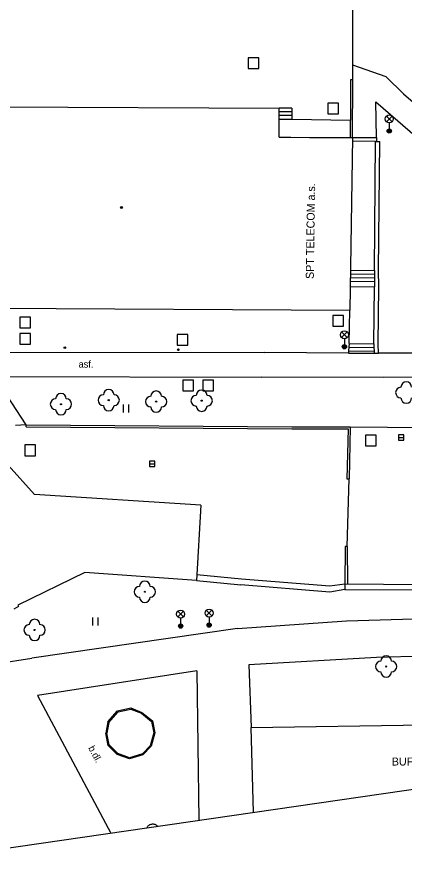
# Model space of a CAD drawing. Extents: x -641829 to -641525, y -1114855 to -1114359.
# Drawn here: x -641668.4 to -641632.1, y -1114854.7 to -1114774 of the extents above; entities that cross this region are included whole.
import ezdxf

# ---------------------------------------------------------------- set-up
doc = ezdxf.new("R2010")
doc.units = 0
for name, color, linetype in [('Vrstva 1', 7, 'Continuous'), ('Vrstva 10', 7, 'Continuous'), ('Vrstva 11', 7, 'Continuous'), ('Vrstva 20', 7, 'Continuous'), ('Vrstva 22', 7, 'Continuous'), ('Vrstva 26', 7, 'Continuous'), ('Vrstva 27', 7, 'Continuous'), ('Vrstva 33', 7, 'Continuous'), ('Vrstva 36', 7, 'Continuous'), ('Vrstva 39', 7, 'Continuous'), ('Vrstva 40', 7, 'Continuous'), ('Vrstva 41', 7, 'Continuous'), ('Vrstva 5', 7, 'Continuous'), ('Vrstva 7', 7, 'Continuous'), ('Vrstva 8', 7, 'Continuous')]:
    doc.layers.add(name, color=color, linetype=linetype)

msp = doc.modelspace()

# ---------------------------------------------------------------- linework, layer by layer
at = {"layer": 'Vrstva 1'}
msp.add_line((-641689.21, -1114854.71), (-641533.66, -1114832.21), dxfattribs=at)
at = {"layer": 'Vrstva 10'}
for p, q in [((-641633.81, -1114779.59), (-641636.93, -1114778.5)), ((-641632.18, -1114781.17), (-641633.81, -1114779.59)), ((-641632.18, -1114781.17), (-641620.12, -1114791.56)), ((-641637.17, -1114812.37), (-641622.59, -1114812.52))]:
    msp.add_line(p, q, dxfattribs=at)
at = {"layer": 'Vrstva 11'}
for p, q in [((-641634.75, -1114781.92), (-641627.17, -1114788.53)), ((-641634.71, -1114785.26), (-641634.75, -1114781.92)), ((-641642.62, -1114782.51), (-641643.82, -1114782.5)), ((-641642.62, -1114782.86), (-641643.82, -1114782.85)), ((-641642.62, -1114782.51), (-641642.62, -1114782.86)), ((-641642.62, -1114782.86), (-641642.62, -1114783.21)), ((-641642.62, -1114783.21), (-641643.82, -1114783.2)), ((-641643.82, -1114783.54), (-641642.62, -1114783.55)), ((-641642.62, -1114783.21), (-641642.62, -1114783.55)), ((-641642.62, -1114783.55), (-641637.14, -1114783.65)), ((-641636.95, -1114785.27), (-641634.71, -1114785.26)), ((-641634.71, -1114785.26), (-641634.71, -1114785.65)), ((-641634.79, -1114785.65), (-641636.95, -1114785.62)), ((-641634.9, -1114797.71), (-641634.79, -1114785.65)), ((-641634.79, -1114785.65), (-641634.71, -1114785.65)), ((-641634.71, -1114785.65), (-641634.39, -1114785.65)), ((-641634.5, -1114797.71), (-641634.39, -1114785.65)), ((-641637.14, -1114798.03), (-641634.9, -1114798.06)), ((-641637.13, -1114797.68), (-641634.9, -1114797.71)), ((-641634.9, -1114797.71), (-641634.9, -1114798.06)), ((-641634.9, -1114798.06), (-641634.9, -1114798.41)), ((-641634.49, -1114799.24), (-641634.5, -1114797.71)), ((-641637.15, -1114798.73), (-641634.89, -1114798.76)), ((-641637.14, -1114798.38), (-641634.9, -1114798.41)), ((-641634.9, -1114798.41), (-641634.89, -1114798.76)), ((-641634.89, -1114798.76), (-641634.89, -1114799.24)), ((-641637.16, -1114799.21), (-641634.89, -1114799.24)), ((-641634.94, -1114804.59), (-641634.89, -1114799.24)), ((-641634.54, -1114804.59), (-641634.49, -1114799.24)), ((-641637.26, -1114804.56), (-641637.19, -1114801.45)), ((-641637.26, -1114804.56), (-641637.29, -1114804.91)), ((-641637.26, -1114804.56), (-641634.94, -1114804.59)), ((-641634.94, -1114804.59), (-641634.94, -1114804.94)), ((-641634.53, -1114805.48), (-641634.54, -1114804.59)), ((-641670.92, -1114805.37), (-641645.18, -1114805.42)), ((-641637.34, -1114805.48), (-641645.18, -1114805.42)), ((-641637.32, -1114805.26), (-641637.34, -1114805.48)), ((-641637.34, -1114805.48), (-641634.93, -1114805.48)), ((-641637.29, -1114804.91), (-641637.32, -1114805.26)), ((-641637.32, -1114805.26), (-641634.93, -1114805.29)), ((-641637.29, -1114804.91), (-641634.94, -1114804.94)), ((-641634.94, -1114804.94), (-641634.93, -1114805.29)), ((-641634.93, -1114805.29), (-641634.93, -1114805.48)), ((-641634.93, -1114805.48), (-641634.53, -1114805.48)), ((-641621.75, -1114805.43), (-641634.53, -1114805.48)), ((-641670.49, -1114807.66), (-641645.43, -1114807.71)), ((-641667.52, -1114812.18), (-641670.49, -1114807.66)), ((-641634.02, -1114807.75), (-641645.43, -1114807.71)), ((-641621.92, -1114807.67), (-641634.02, -1114807.75)), ((-641637.68, -1114827.61), (-641611.8, -1114827.76)), ((-641647.71, -1114831.26), (-641637.5, -1114830.54)), ((-641637.5, -1114830.54), (-641620.39, -1114830.05)), ((-641647.71, -1114831.26), (-641667, -1114834.04)), ((-641612.75, -1114833.36), (-641634.7, -1114833.98)), ((-641681.11, -1114836.22), (-641667, -1114834.04)), ((-641634.7, -1114833.98), (-641646.67, -1114834.67)), ((-641651.53, -1114835.24), (-641666.47, -1114837.53)), ((-641651.53, -1114835.24), (-641651.335, -1114849.232)), ((-641646.67, -1114834.67), (-641646.44, -1114840.53)), ((-641666.47, -1114837.53), (-641659.603, -1114850.427)), ((-641659.86, -1114840.02), (-641658.96, -1114838.98)), ((-641659.77, -1114840.06), (-641658.91, -1114839.07)), ((-641658.96, -1114838.98), (-641657.71, -1114838.71)), ((-641658.91, -1114839.07), (-641657.72, -1114838.81)), ((-641657.72, -1114838.81), (-641656.72, -1114839.21)), ((-641657.71, -1114838.71), (-641656.67, -1114839.12)), ((-641656.72, -1114839.21), (-641655.79, -1114839.98)), ((-641656.67, -1114839.12), (-641655.7, -1114839.92)), ((-641659.86, -1114840.02), (-641660.07, -1114841.08)), ((-641659.77, -1114840.06), (-641659.97, -1114841.08)), ((-641655.79, -1114839.98), (-641655.57, -1114841.03)), ((-641655.7, -1114839.92), (-641655.47, -1114841.03)), ((-641655.57, -1114841.03), (-641655.89, -1114842.25)), ((-641655.47, -1114841.03), (-641655.8, -1114842.3)), ((-641659.84, -1114842.22), (-641660.07, -1114841.08)), ((-641659.75, -1114842.17), (-641659.97, -1114841.08)), ((-641658.98, -1114843.07), (-641659.84, -1114842.22)), ((-641658.92, -1114842.98), (-641659.75, -1114842.17)), ((-641655.89, -1114842.25), (-641656.63, -1114843.01)), ((-641655.8, -1114842.3), (-641656.58, -1114843.1)), ((-641657.84, -1114843.48), (-641658.98, -1114843.07)), ((-641657.84, -1114843.37), (-641658.92, -1114842.98)), ((-641656.63, -1114843.01), (-641657.84, -1114843.37)), ((-641656.58, -1114843.1), (-641657.84, -1114843.48)), ((-641656.214, -1114849.937), (-641656.19, -1114849.89)), ((-641656.19, -1114849.89), (-641656.16, -1114849.83)), ((-641656.16, -1114849.83), (-641656.11, -1114849.77)), ((-641656.11, -1114849.77), (-641656.06, -1114849.73)), ((-641656.06, -1114849.73), (-641656.01, -1114849.68)), ((-641656.01, -1114849.68), (-641655.95, -1114849.64)), ((-641655.95, -1114849.64), (-641655.89, -1114849.61)), ((-641655.89, -1114849.61), (-641655.82, -1114849.59)), ((-641655.82, -1114849.59), (-641655.76, -1114849.58)), ((-641655.76, -1114849.58), (-641655.69, -1114849.57)), ((-641655.69, -1114849.57), (-641655.62, -1114849.57)), ((-641655.62, -1114849.57), (-641655.55, -1114849.58)), ((-641655.55, -1114849.58), (-641655.48, -1114849.6)), ((-641655.48, -1114849.6), (-641655.42, -1114849.62)), ((-641655.42, -1114849.62), (-641655.36, -1114849.65)), ((-641655.36, -1114849.65), (-641655.3, -1114849.69)), ((-641655.3, -1114849.69), (-641655.25, -1114849.74)), ((-641655.25, -1114849.74), (-641655.2, -1114849.79)), ((-641655.2, -1114849.79), (-641655.2, -1114849.79))]:
    msp.add_line(p, q, dxfattribs=at)
msp.add_lwpolyline([(-641612.23, -1114827.33), (-641637.68, -1114827.12)], dxfattribs=at)
at = {"layer": 'Vrstva 20'}
for centre, radius in [((-641663.9, -1114804.96), 0.075), ((-641663.9, -1114804.96), 0.0204), ((-641653.26, -1114805.15), 0.075), ((-641653.26, -1114805.15), 0.0204)]:
    msp.add_circle(centre, radius, dxfattribs=at)
at = {"layer": 'Vrstva 22'}
for centre in [(-641664.26, -1114810.25), (-641659.79, -1114809.87), (-641655.34, -1114810.01), (-641651.08, -1114809.92), (-641656.4, -1114827.82), (-641666.73, -1114831.4), (-641633.8, -1114834.82)]:
    msp.add_circle(centre, 0.05, dxfattribs=at)
for centre, start, end in [((-641632.41, -1114809.16), 90, 270), ((-641631.91, -1114808.66), 0, 180), ((-641664.26, -1114809.75), 0, 180), ((-641660.29, -1114809.87), 90, 270), ((-641659.79, -1114809.37), 0, 180), ((-641659.29, -1114809.87), 270, 90), ((-641655.84, -1114810.01), 90, 270), ((-641655.34, -1114809.51), 0, 180), ((-641654.84, -1114810.01), 270, 90), ((-641651.58, -1114809.92), 90, 270), ((-641651.08, -1114809.42), 0, 180), ((-641650.58, -1114809.92), 270, 90), ((-641664.76, -1114810.25), 90, 270), ((-641663.76, -1114810.25), 270, 90), ((-641631.91, -1114809.66), 180, 0), ((-641664.26, -1114810.75), 180, 0), ((-641659.79, -1114810.37), 180, 0), ((-641655.34, -1114810.51), 180, 0), ((-641651.08, -1114810.42), 180, 0), ((-641656.4, -1114827.32), 0, 180), ((-641656.9, -1114827.82), 90, 270), ((-641655.9, -1114827.82), 270, 90), ((-641656.4, -1114828.32), 180, 0), ((-641666.73, -1114830.9), 0, 180), ((-641667.23, -1114831.4), 90, 270), ((-641666.23, -1114831.4), 270, 90), ((-641666.73, -1114831.9), 180, 0), ((-641634.3, -1114834.82), 90, 270), ((-641633.8, -1114834.32), 0, 180), ((-641633.3, -1114834.82), 270, 90), ((-641633.8, -1114835.32), 180, 0)]:
    msp.add_arc(centre, 0.5, start, end, dxfattribs=at)
at = {"layer": 'Vrstva 26'}
for points in [[(-641645.71, -1114777.79), (-641646.71, -1114777.79), (-641646.71, -1114778.79), (-641645.71, -1114778.79)], [(-641638.25, -1114782.04), (-641639.25, -1114782.04), (-641639.25, -1114783.04), (-641638.25, -1114783.04)], [(-641668.1, -1114803.1), (-641667.1, -1114803.1), (-641667.1, -1114802.1), (-641668.1, -1114802.1)], [(-641638.79, -1114802.95), (-641637.79, -1114802.95), (-641637.79, -1114801.95), (-641638.79, -1114801.95)], [(-641668.11, -1114804.63), (-641667.11, -1114804.63), (-641667.11, -1114803.63), (-641668.11, -1114803.63)], [(-641653.38, -1114804.71), (-641652.38, -1114804.71), (-641652.38, -1114803.71), (-641653.38, -1114803.71)], [(-641652.85, -1114809), (-641651.85, -1114809), (-641651.85, -1114808), (-641652.85, -1114808)], [(-641650.96, -1114809), (-641649.96, -1114809), (-641649.96, -1114808), (-641650.96, -1114808)], [(-641635.72, -1114814.16), (-641634.72, -1114814.16), (-641634.72, -1114813.16), (-641635.72, -1114813.16)], [(-641667.66, -1114815.07), (-641666.66, -1114815.07), (-641666.66, -1114814.07), (-641667.66, -1114814.07)]]:
    msp.add_lwpolyline(points, close=True, dxfattribs=at)
at = {"layer": 'Vrstva 27'}
for p, q in [((-641632.65, -1114813.36), (-641632.15, -1114813.36)), ((-641655.97, -1114815.83), (-641655.47, -1114815.83))]:
    msp.add_line(p, q, dxfattribs=at)
for points in [[(-641632.65, -1114813.61), (-641632.15, -1114813.61), (-641632.15, -1114813.11), (-641632.65, -1114813.11)], [(-641655.97, -1114816.08), (-641655.47, -1114816.08), (-641655.47, -1114815.58), (-641655.97, -1114815.58)]]:
    msp.add_lwpolyline(points, close=True, dxfattribs=at)
at = {"layer": 'Vrstva 33'}
for p, q in [((-641633.774, -1114783.79), (-641633.246, -1114783.26)), ((-641633.774, -1114783.26), (-641633.246, -1114783.79)), ((-641633.51, -1114783.9), (-641633.51, -1114784.65)), ((-641637.974, -1114804.01), (-641637.446, -1114803.48)), ((-641637.974, -1114803.48), (-641637.446, -1114804.01)), ((-641637.71, -1114804.12), (-641637.71, -1114804.87)), ((-641653.314, -1114830.18), (-641652.786, -1114829.65)), ((-641653.314, -1114829.65), (-641652.786, -1114830.18)), ((-641650.644, -1114830.08), (-641650.116, -1114829.55)), ((-641650.644, -1114829.55), (-641650.116, -1114830.08)), ((-641653.05, -1114830.29), (-641653.05, -1114831.04)), ((-641650.38, -1114830.19), (-641650.38, -1114830.94))]:
    msp.add_line(p, q, dxfattribs=at)
for centre, radius in [((-641633.51, -1114783.525), 0.375), ((-641633.51, -1114784.65), 0.2), ((-641633.51, -1114784.65), 0.145), ((-641633.51, -1114784.65), 0.0876), ((-641637.71, -1114803.745), 0.375), ((-641637.71, -1114804.87), 0.2), ((-641637.71, -1114804.87), 0.145), ((-641637.71, -1114804.87), 0.0876), ((-641653.05, -1114829.915), 0.375), ((-641650.38, -1114829.815), 0.375), ((-641653.05, -1114831.04), 0.2), ((-641653.05, -1114831.04), 0.145), ((-641653.05, -1114831.04), 0.0876), ((-641650.38, -1114830.94), 0.2), ((-641650.38, -1114830.94), 0.145), ((-641650.38, -1114830.94), 0.0876)]:
    msp.add_circle(centre, radius, dxfattribs=at)
at = {"layer": 'Vrstva 36'}
for p, q in [((-641658.394, -1114811.014), (-641658.394, -1114810.262)), ((-641657.894, -1114811.014), (-641657.894, -1114810.262)), ((-641661.274, -1114830.984), (-641661.274, -1114830.232)), ((-641660.774, -1114830.984), (-641660.774, -1114830.232))]:
    msp.add_line(p, q, dxfattribs=at)
at = {"layer": 'Vrstva 39'}
for radius in [0.09, 0.0398]:
    msp.add_circle((-641658.59, -1114791.81), radius, dxfattribs=at)
at = {"layer": 'Vrstva 5'}
for p, q in [((-641680.28, -1114782.33), (-641643.82, -1114782.5)), ((-641643.82, -1114783.54), (-641643.82, -1114782.5)), ((-641643.83, -1114785.24), (-641643.82, -1114783.54)), ((-641643.83, -1114785.24), (-641642.73, -1114785.24)), ((-641642.73, -1114785.24), (-641640.98, -1114785.25)), ((-641640.98, -1114785.25), (-641636.95, -1114785.27)), ((-641636.95, -1114785.27), (-641637.19, -1114801.45)), ((-641680.53, -1114801.2), (-641637.19, -1114801.45)), ((-641669.21, -1114815.95), (-641666.73, -1114818.7)), ((-641651.16, -1114819.72), (-641666.73, -1114818.7)), ((-641651.16, -1114819.72), (-641651.56, -1114826.77)), ((-641662.02, -1114826.02), (-641668.29, -1114829.07)), ((-641651.56, -1114826.77), (-641662.02, -1114826.02)), ((-641668.23, -1114829.2), (-641668.66, -1114829.45)), ((-641668.29, -1114829.07), (-641668.23, -1114829.2)), ((-641646.44, -1114840.53), (-641609.97, -1114839.96)), ((-641646.237, -1114848.494), (-641646.44, -1114840.53))]:
    msp.add_line(p, q, dxfattribs=at)
at = {"layer": 'Vrstva 7'}
for p, q in [((-641637.13, -1114779.85), (-641637.14, -1114783.65)), ((-641636.93, -1114779.85), (-641637.13, -1114779.85)), ((-641636.95, -1114785.27), (-641636.93, -1114779.85)), ((-641637.15, -1114785.27), (-641637.14, -1114783.65)), ((-641667.52, -1114812.18), (-641642.64, -1114812.36)), ((-641667.52, -1114812.38), (-641667.52, -1114812.18)), ((-641667.52, -1114812.38), (-641642.64, -1114812.56)), ((-641642.64, -1114812.36), (-641637.17, -1114812.37)), ((-641642.64, -1114812.56), (-641637.37, -1114812.57)), ((-641637.37, -1114812.57), (-641637.47, -1114817.25)), ((-641637.17, -1114812.37), (-641637.27, -1114817.25)), ((-641637.47, -1114817.25), (-641637.27, -1114817.25)), ((-641637.65, -1114823.59), (-641637.68, -1114827.12)), ((-641637.45, -1114823.59), (-641637.65, -1114823.59)), ((-641637.45, -1114823.59), (-641637.43, -1114827.12)), ((-641647.36, -1114826.63), (-641651.53, -1114826.22)), ((-641651.56, -1114826.77), (-641647.4, -1114827.18)), ((-641639.06, -1114827.85), (-641647.4, -1114827.18)), ((-641639.08, -1114827.3), (-641647.36, -1114826.63)), ((-641637.68, -1114827.12), (-641639.08, -1114827.3)), ((-641637.68, -1114827.12), (-641637.68, -1114827.61)), ((-641637.68, -1114827.61), (-641639.06, -1114827.85))]:
    msp.add_line(p, q, dxfattribs=at)
at = {"layer": 'Vrstva 8'}
for p, q in [((-641636.93, -1114779.85), (-641636.92, -1114771.92)), ((-641667.52, -1114812.18), (-641668.53, -1114812.24)), ((-641637.45, -1114823.59), (-641637.27, -1114817.25))]:
    msp.add_line(p, q, dxfattribs=at)

# ---------------------------------------------------------------- texts
at = {"layer": 'Vrstva 40'}
for s, rotation, p in [('asf.', 359.88568, (-641662.62, -1114806.82)), ('b.dl.', 298.32939, (-641661.73, -1114842.46))]:
    msp.add_text(s, height=0.65, rotation=rotation, dxfattribs=at).set_placement(p)
at = {"layer": 'Vrstva 41'}
msp.add_text('SPT TELECOM a.s.', height=0.7499, rotation=89.15019, dxfattribs=at).set_placement((-641640.58, -1114798.52))
msp.add_text('BUFET VESNA', height=0.75, dxfattribs=at).set_placement((-641633.27, -1114844.1))

doc.saveas('drawing.dxf')
